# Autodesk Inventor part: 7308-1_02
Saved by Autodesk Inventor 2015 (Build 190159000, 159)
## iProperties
Created: 2021-01
Part Number: 7308-1_02
Checked By: TraceParts S.A.
Material: Generic
Catalog Web Link: www.traceparts.com
Document SubType Name: Modeling
Designer: TraceParts
Density: 1 g/cm^3
Appearance: Default
Company: TraceParts S.A.
Author: TraceParts
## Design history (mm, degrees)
feature "7308-1_02.ipt"
body "Solid1"
